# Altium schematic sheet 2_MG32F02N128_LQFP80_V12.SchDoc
size 513 x 335 mm
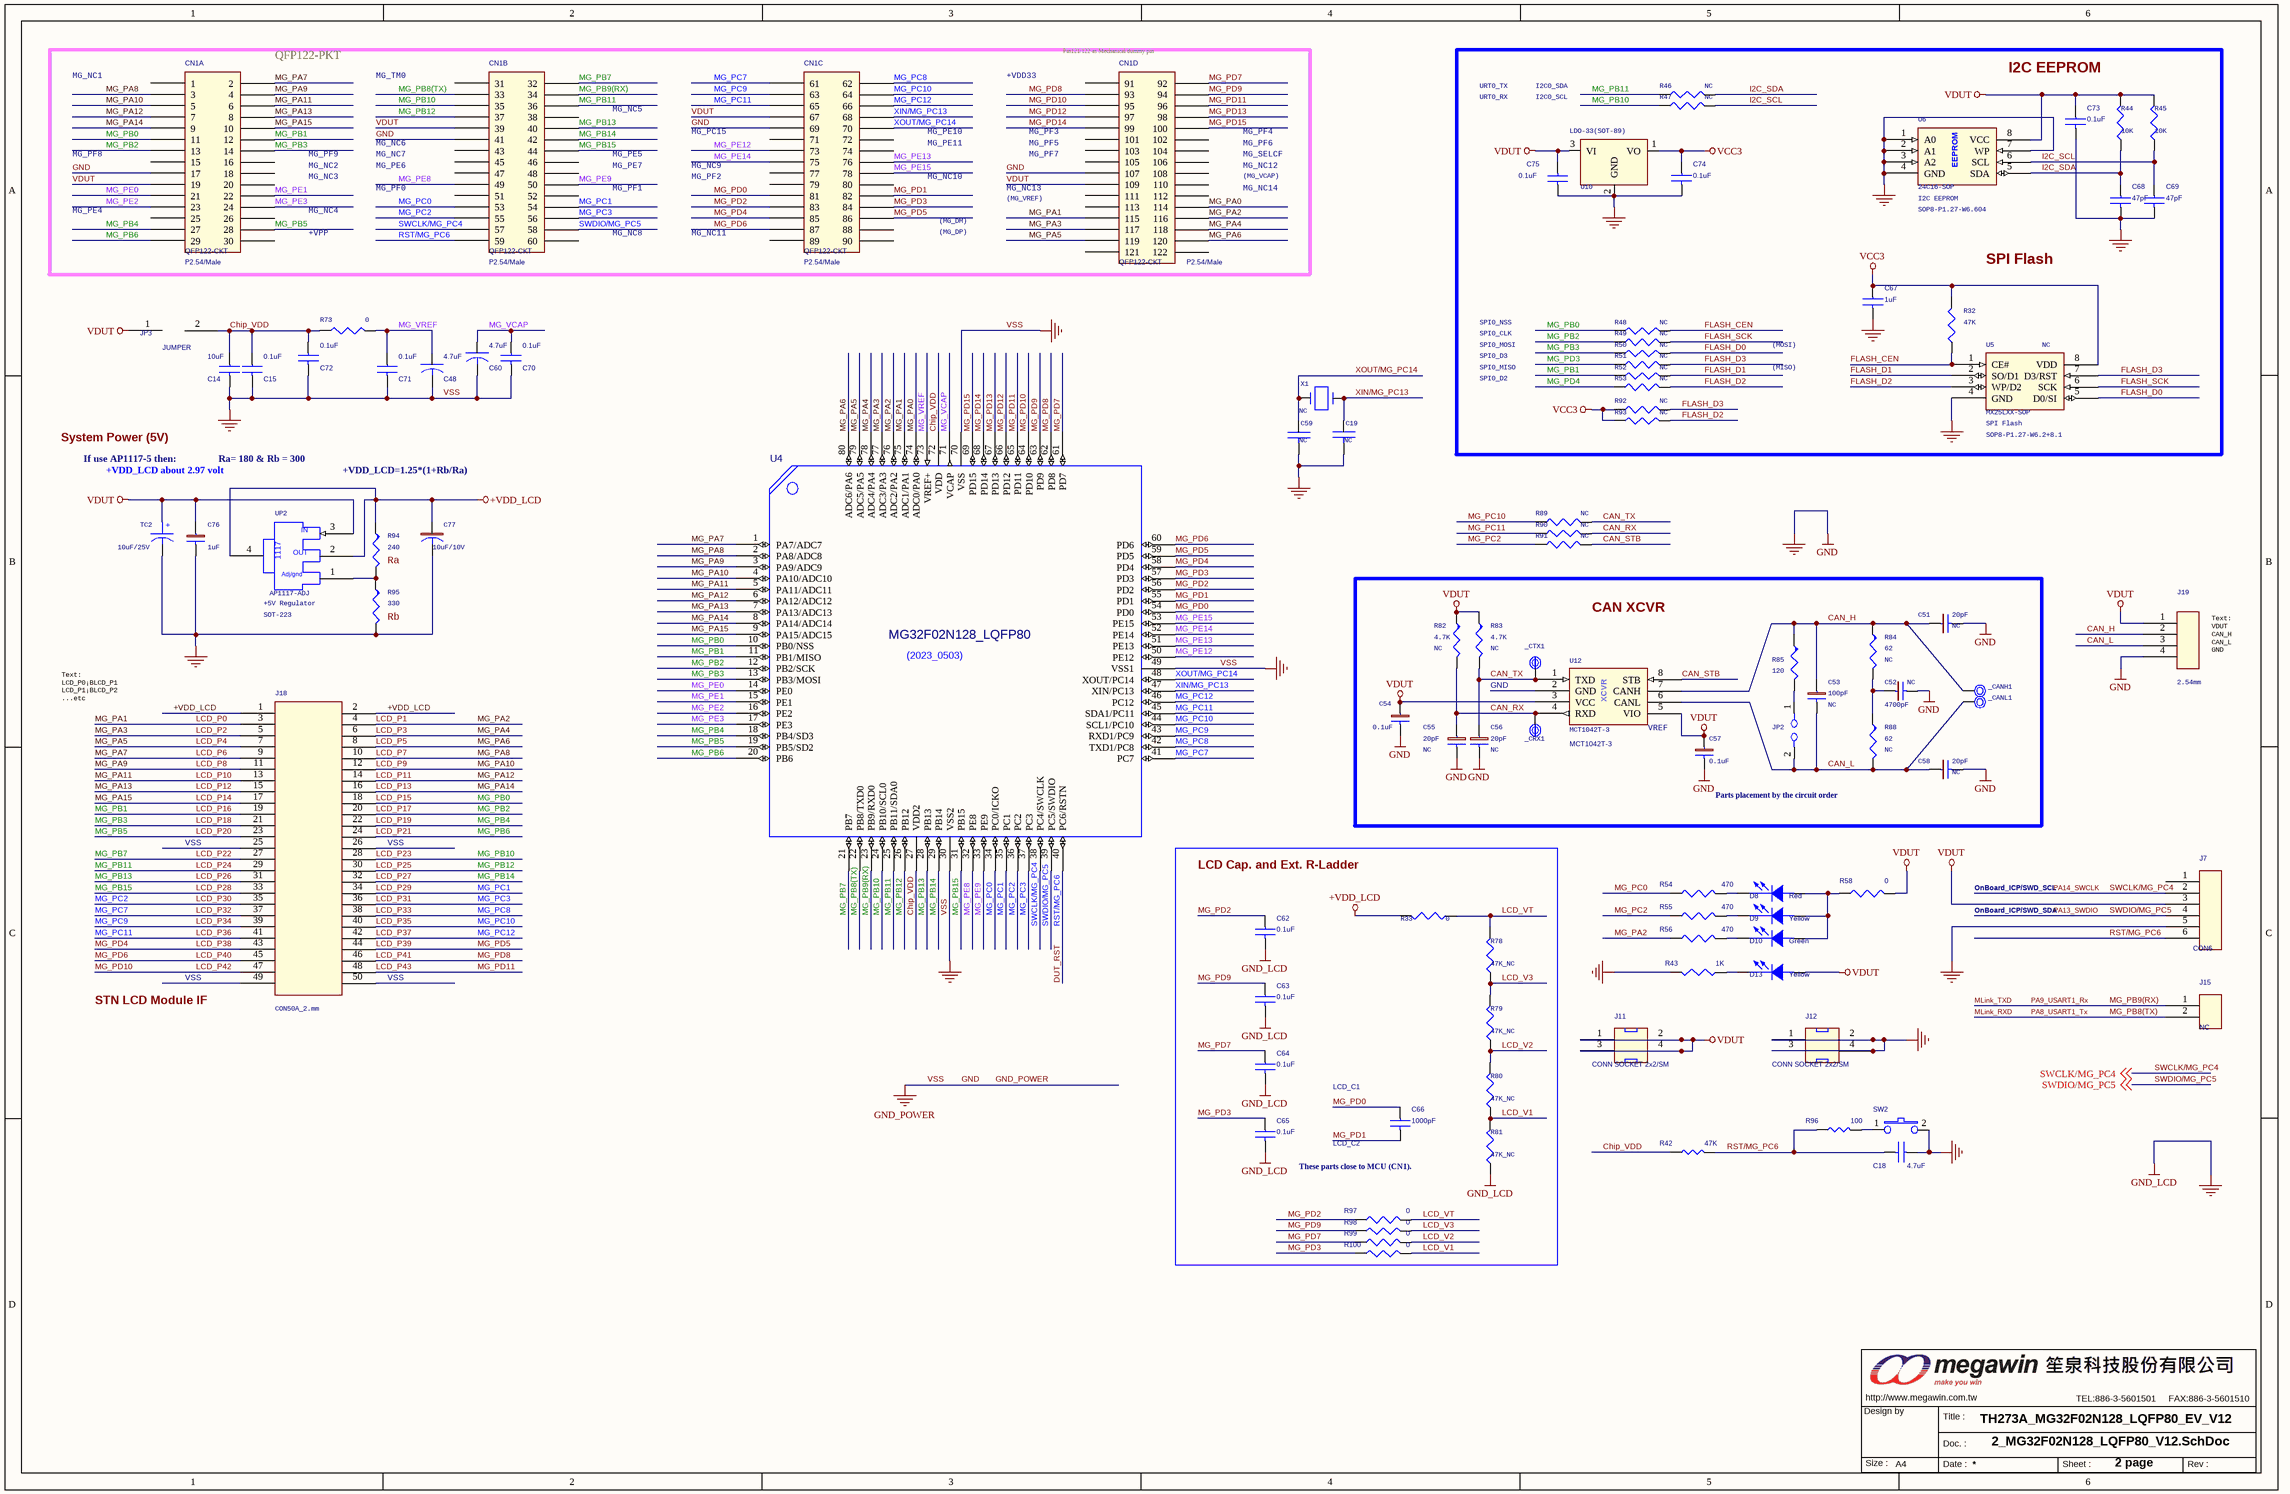
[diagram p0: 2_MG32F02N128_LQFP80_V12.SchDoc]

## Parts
_CANH1  TP-COIL  [TPH60-COIL]  (value not drawn)
_CANL1  TP-COIL  [TPH60-COIL]  (value not drawn)
_CRX1  TP-COIL  [TPH60-COIL]  (value not drawn)
_CTX1  TP-COIL  [TPH60-COIL]  (value not drawn)
C14  10uF  [C-0603]
C15  0.1uF  [C-0603]
C18  4.7uF  [C-0603]
C19  NC  [C-0603]
C48  4.7uF  [C-0805]
C51  20pF  Assembly: NC  [C-0603]
C52  4700pF  Assembly: NC  [C-0603]
C53  100pF  Assembly: NC  [C-0603]
C54  0.1uF  [C-0603]
C55  20pF  Assembly: NC  [C-0603]
C56  20pF  Assembly: NC  [C-0603]
C57  0.1uF  [C-0603]
C58  20pF  Assembly: NC  [C-0603]
C59  NC  [C-0603]
C60  4.7uF  [C-0805]
C62  0.1uF  [C-0603]
C63  0.1uF  [C-0603]
C64  0.1uF  [C-0603]
C65  0.1uF  [C-0603]
C66  1000pF  [C-0603]
C67  1uF  [C-0603]
C68  47pF  [C-0603]
C69  47pF  [C-0603]
C70  0.1uF  [C-0603]
C71  0.1uF  [C-0603]
C72  0.1uF  [C-0603]
C73  0.1uF  [C-0603]
C74  0.1uF  [C-0603]
C75  0.1uF  [C-0603]
C76  1uF  [C-0603]
C77  10uF/10V  [C-0805]
CN1  QFP122-CKT  Package: P2.54/Male  [QFP122-P2.54-CKT]  (parts A,B,C,D of 4)
D8  Red  [0805D]
D9  Yellow  [0805D]
D10  Green  [0805D]
D13  Yellow  [0805D]
J7  CON6  [PS6P254]
J11  CONN SOCKET 2x2/SM  [PS2X2P254]
J12  CONN SOCKET 2x2/SM  [PS2X2P254]
J15  NC  [PS2P254]
J18  CON50A_2.mm  [HD25X2-P2.0]
J19  2.54mm  [PS4P254]
JP2  JUMPER  [SIP2-P2.54-JUMPER]  (value not drawn)
JP3  JUMPER  [PS2P254]
MW1  OrgAddr3: TEL:886-3-5601501     FAX:886-3-5601510  [MEGAWIN_3.4_1]  (hidden comment: MW-A4)  (graphical)
R32  47K  [R-0603]
R33  0  [R-0603]
R42  47K  [R-0603]
R43  1K  [R-0603]
R44  10K  [R-0603]
R45  10K  [R-0603]
R46  NC  [R-0603]
R47  NC  [R-0603]
R48  NC  [R-0603]
R49  NC  [R-0603]
R50  NC  [R-0603]
R51  NC  [R-0603]
R52  NC  [R-0603]
R53  NC  [R-0603]
R54  470  [R-0603]
R55  470  [R-0603]
R56  470  [R-0603]
R58  0  [R-0603]
R73  0  [R-0603]
R78  47K_NC  [R-0603]
R79  47K_NC  [R-0603]
R80  47K_NC  [R-0603]
R81  47K_NC  [R-0603]
R82  4.7K  Assembly: NC  [R-0603]
R83  4.7K  Assembly: NC  [R-0603]
R84  62  Assembly: NC  [R-0603]
R85  120  [R-0603]
R88  62  Assembly: NC  [R-0603]
R89  NC  [R-0603]
R90  NC  [R-0603]
R91  NC  [R-0603]
R92  NC  [R-0603]
R93  NC  [R-0603]
R94  240  [R-0603]
R95  330  [R-0603]
R96  100  [R-0603]
R97  0  [R-0603]
R98  0  [R-0603]
R99  0  [R-0603]
R100  0  [R-0603]
SW2  SW TACT-SPST  [SW_T_2P]  (value not drawn)
TC2  10uF/25V  [C-1812+]
U4  MG32F02N128_LQFP80  [QFP80-P0.4-Z12X12]
U5  MX25LXX-SOP  Function: SPI Flash  Assembly: NC  [SOP8-P1.27-W6.2+8.1]
U6  24C16-SOP  Function: I2C EEPROM  [SOP8-P1.27-W6.604]
U10  LDO-33(SOT-89)  [SOT89]
U12  MCT1042T-3  [SOP8-P1.27-W6.2]
UP2  AP1117-ADJ  Package: SOT-223  Function: +5V Regulator  [SOT223H\3P]
X1  NC  [X49U]

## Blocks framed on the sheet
QFP122-PKT: CN1
CAN XCVR: _CANH1 _CANL1 _CRX1 _CTX1 C51-C58 JP2 R82-R85 R88 U12
LCD Cap. and Ext. R-Ladder: C62-C66 R33 R78-R81 R97-R100

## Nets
+VDD_LCD: C77.1 J18.1 J18.2 R33.2 R94.1 UP2.2(OUT) UP2.4(VOUT)
GND: C14.2 C15.2 C18.1 C19.2 C48.2 C51.2 C52.2 C54.2 C55.2 C56.2 C57.2 C58.2 C59.2 C60.2 C62.2 C63.2 C64.2 C65.2 C67.2 C68.2 C69.2 C70.2 C71.2 C72.2 C73.2 C74.2 C75.2 C76.2 C77.2 CN1.17 CN1.41 CN1.69 CN1.107 J7.5 J12.1 J12.2 J12.3 J12.4 J18.25 J18.26 J18.49 J18.50 J19.4 R43.1 R81.1 R95.2 SW2.2 TC2.2 U4.30(VSS2) U4.49(VSS1) U4.70(VSS) U5.4(GND) U6.1(A0) U6.2(A1) U6.3(A2) U6.4(GND) U6.7(WP) U10.2(GND) U12.2(GND)  [also labelled GND_LCD, GND_POWER, VSS]
VCC3: C67.1 C74.1 R32.2 R92.1 R93.1 U5.8(VDD) U10.1(VO)
VDUT: C54.1 C57.1 C73.1 C75.1 C76.1 CN1.19 CN1.39 CN1.67 CN1.109 D13.1(ANODE) J7.3 J11.1 J11.2 J11.3 J11.4 J19.1 JP3.1 R44.2 R45.2 R58.2 R82.1 R83.1 TC2.1 U6.8(VCC) U10.3(VI) U12.3(VCC) U12.5(VIO) UP2.3(IN)
CAN_H: _CANH1.1 C51.1 C53.1 J19.2 R84.1 R85.1 U12.7(CANH)
CAN_L: _CANL1.1 C53.2 C58.1 J19.3 JP2.2 R88.2 U12.6(CANL)
CAN_RX: _CRX1.1 C55.1 R82.2 R90.2 U12.4(RXD)
CAN_STB: R91.2 U12.8(STB)
CAN_TX: _CTX1.1 C56.1 R83.2 R89.2 U12.1(TXD)
Chip_VDD: C14.1 C15.1 C72.1 JP3.2 R42.1 R73.2 U4.27(VDD2) U4.72(VDD)
DUT_RST: C18.2 CN1.59 J7.6 R42.2 R96.1 U4.40(PC6/RSTN)  [also labelled RST/MG_PC6]
FLASH_CEN: R32.1 R48.2 U5.1(CE#)
FLASH_D0: R50.2 U5.5(D0/SI)
FLASH_D1: R52.2 U5.2(SO/D1)
FLASH_D2: R53.2 R93.2 U5.3(WP/D2)
FLASH_D3: R51.2 R92.2 U5.7(D3/RST)
FLASH_SCK: R49.2 U5.6(SCK)
I2C_SCL: C69.1 R45.1 R47.2 U6.6(SCL)
I2C_SDA: C68.1 R44.1 R46.2 U6.5(SDA)
LCD_P0: CN1.115 J18.3 U4.75(ADC1/PA1)  [also labelled MG_PA1]
LCD_P1: CN1.116 J18.4 R56.1 U4.76(ADC2/PA2)  [also labelled MG_PA2]
LCD_P2: CN1.117 J18.5 U4.77(ADC3/PA3)  [also labelled MG_PA3]
LCD_P3: CN1.118 J18.6 U4.78(ADC4/PA4)  [also labelled MG_PA4]
LCD_P4: CN1.119 J18.7 U4.79(ADC5/PA5)  [also labelled MG_PA5]
LCD_P5: CN1.120 J18.8 U4.80(ADC6/PA6)  [also labelled MG_PA6]
LCD_P6: CN1.2 J18.9 U4.1(PA7/ADC7)  [also labelled MG_PA7]
LCD_P7: CN1.3 J18.10 U4.2(PA8/ADC8)  [also labelled MG_PA8]
LCD_P8: CN1.4 J18.11 U4.3(PA9/ADC9)  [also labelled MG_PA9]
LCD_P9: CN1.5 J18.12 U4.4(PA10/ADC10)  [also labelled MG_PA10]
LCD_P10: CN1.6 J18.13 U4.5(PA11/ADC11)  [also labelled MG_PA11]
LCD_P11: CN1.7 J18.14 U4.6(PA12/ADC12)  [also labelled MG_PA12]
LCD_P12: CN1.8 J18.15 U4.7(PA13/ADC13)  [also labelled MG_PA13]
LCD_P13: CN1.9 J18.16 U4.8(PA14/ADC14)  [also labelled MG_PA14]
LCD_P14: CN1.10 J18.17 U4.9(PA15/ADC15)  [also labelled MG_PA15]
LCD_P15: CN1.11 J18.18 R48.1 U4.10(PB0/NSS)  [also labelled MG_PB0]
LCD_P16: CN1.12 J18.19 R52.1 U4.11(PB1/MISO)  [also labelled MG_PB1]
LCD_P17: CN1.13 J18.20 R49.1 U4.12(PB2/SCK)  [also labelled MG_PB2]
LCD_P18: CN1.14 J18.21 R50.1 U4.13(PB3/MOSI)  [also labelled MG_PB3]
LCD_P19: CN1.27 J18.22 U4.18(PB4/SD3)  [also labelled MG_PB4]
LCD_P20: CN1.28 J18.23 U4.19(PB5/SD2)  [also labelled MG_PB5]
LCD_P21: CN1.29 J18.24 U4.20(PB6)  [also labelled MG_PB6]
LCD_P22: CN1.32 J18.27 U4.21(PB7)  [also labelled MG_PB7]
LCD_P23: CN1.35 J18.28 R47.1 U4.24(PB10/SCL0)  [also labelled MG_PB10]
LCD_P24: CN1.36 J18.29 R46.1 U4.25(PB11/SDA0)  [also labelled MG_PB11]
LCD_P25: CN1.37 J18.30 U4.26(PB12)  [also labelled MG_PB12]
LCD_P26: CN1.40 J18.31 U4.28(PB13)  [also labelled MG_PB13]
LCD_P27: CN1.42 J18.32 U4.29(PB14)  [also labelled MG_PB14]
LCD_P28: CN1.44 J18.33 U4.31(PB15)  [also labelled MG_PB15]
LCD_P29: CN1.54 J18.34 U4.35(PC1)  [also labelled MG_PC1]
LCD_P30: CN1.55 J18.35 R55.1 R91.1 U4.36(PC2)  [also labelled MG_PC2]
LCD_P31: CN1.56 J18.36 U4.37(PC3)  [also labelled MG_PC3]
LCD_P32: CN1.61 J18.37 U4.41(PC7)  [also labelled MG_PC7]
LCD_P33: CN1.62 J18.38 U4.42(TXD1/PC8)  [also labelled MG_PC8]
LCD_P34: CN1.63 J18.39 U4.43(RXD1/PC9)  [also labelled MG_PC9]
LCD_P35: CN1.64 J18.40 R89.1 U4.44(SCL1/PC10)  [also labelled MG_PC10]
LCD_P36: CN1.65 J18.41 R90.1 U4.45(SDA1/PC11)  [also labelled MG_PC11]
LCD_P37: CN1.66 J18.42 U4.46(PC12)  [also labelled MG_PC12]
LCD_P38: CN1.85 J18.43 R53.1 U4.58(PD4)  [also labelled MG_PD4]
LCD_P39: CN1.86 J18.44 U4.59(PD5)  [also labelled MG_PD5]
LCD_P40: CN1.87 J18.45 U4.60(PD6)  [also labelled MG_PD6]
LCD_P41: CN1.93 J18.46 U4.62(PD8)  [also labelled MG_PD8]
LCD_P42: CN1.95 J18.47 U4.64(PD10)  [also labelled MG_PD10]
LCD_P43: CN1.96 J18.48 U4.65(PD11)  [also labelled MG_PD11]
LCD_V1: R80.1 R81.2 R100.2
LCD_V2: R79.1 R80.2 R99.2
LCD_V3: R78.1 R79.2 R98.2
LCD_VT: R33.1 R78.2 R97.2
MG_PA0: CN1.114 U4.74(ADC0/PA0)
MG_PB8(TX): CN1.33 J15.2 U4.22(PB8/TXD0)  [also labelled MLink_RXD, PA8_USART1_Tx]
MG_PB9(RX): CN1.34 J15.1 U4.23(PB9/RXD0)  [also labelled MLink_TXD, PA9_USART1_Rx]
MG_PC0: CN1.53 R54.1 U4.34(PC0/ICKO)
MG_PD0: C66.1 CN1.81 U4.54(PD0)
MG_PD1: C66.2 CN1.82 U4.55(PD1)
MG_PD2: C62.1 CN1.83 R97.1 U4.56(PD2)
MG_PD3: C65.1 CN1.84 R51.1 R100.1 U4.57(PD3)
MG_PD7: C64.1 CN1.92 R99.1 U4.61(PD7)
MG_PD9: C63.1 CN1.94 R98.1 U4.63(PD9)
MG_PD12: CN1.97 U4.66(PD12)
MG_PD13: CN1.98 U4.67(PD13)
MG_PD14: CN1.99 U4.68(PD14)
MG_PD15: CN1.100 U4.69(PD15)
MG_PE0: CN1.21 U4.14(PE0)
MG_PE1: CN1.22 U4.15(PE1)
MG_PE2: CN1.23 U4.16(PE2)
MG_PE3: CN1.24 U4.17(PE3)
MG_PE8: CN1.49 U4.32(PE8)
MG_PE9: CN1.50 U4.33(PE9)
MG_PE12: CN1.73 U4.50(PE12)
MG_PE13: CN1.76 U4.51(PE13)
MG_PE14: CN1.75 U4.52(PE14)
MG_PE15: CN1.78 U4.53(PE15)
MG_VCAP: C60.1 C70.1 U4.71(VCAP)
MG_VREF: C48.1 C71.1 R73.1 U4.73(VREF+)
PA13_SWDIO: CN1.58 J7.4 U4.39(PC5/SWDIO) ; off-sheet SWDIO/MG_PC5  [also labelled SWDIO/MG_PC5]
PA14_SWCLK: CN1.57 J7.2 U4.38(PC4/SWCLK) ; off-sheet SWCLK/MG_PC4  [also labelled SWCLK/MG_PC4]
XIN/MG_PC13: C19.1 CN1.68 U4.47(XIN/PC13) X1.2
XOUT/MG_PC14: C59.1 CN1.70 U4.48(XOUT/PC14) X1.1
NetC52_1: C52.1 R84.2 R88.1
NetD8_1: D8.1(ANODE) D9.1(ANODE) D10.1(ANODE) R58.1
NetD8_2: D8.2(CATHODE) R54.2
NetD9_2: D9.2(CATHODE) R55.2
NetD10_2: D10.2(CATHODE) R56.2
NetD13_2: D13.2(CATHODE) R43.2
NetJP2_1: JP2.1 R85.2
NetR94_2: R94.2 R95.1 UP2.1(ADJ)
NetR96_2: R96.2 SW2.1

Not connected (* = marked no-connect by the designer): CN1 1 15 16 18 20 25 26 30 31 38 43 45 46 47 48 51 52 60 71 72 74 77 79 80 88 89 90 91 101 102 103 104 105 106 108 110 111 112 113 121 122; J7 1

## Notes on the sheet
- MG_NC1
- MG_TM0
- +VDD33
- (near CN1) Pin121/122 as Mechanical dummy pin
- URT0_RX
- URT0_TX
- I2C0_SDA
- I2C0_SCL
- I2C EEPROM
- MG_PF8
- MG_PF9
- MG_NC7
- MG_NC6
- MG_NC5
- MG_PE5
- MG_PC15
- MG_PE10
- MG_PE11
- MG_PF3
- MG_PF7
- MG_PF5
- MG_SELCF
- MG_PF4
- MG_PF6
- MG_PE4
- MG_NC2
- MG_NC4
- MG_NC3
- MG_PF0
- MG_PE6
- MG_PF1
- MG_PE7
- MG_NC9
- MG_PF2
- MG_NC10
- (MG_VREF)
- MG_NC13
- MG_NC12
- (MG_VCAP)
- MG_NC14
- +VPP
- MG_NC8
- MG_NC11
- (MG_DM)
- (MG_DP)
- SPI Flash
- SPI0_NSS
- SPI0_D3
- SPI0_CLK
- SPI0_MISO
- SPI0_D2
- SPI0_MOSI
- (MOSI)
- (MISO)
- System Power (5V)
- If use AP1117-5 then:
- +VDD_LCD about 2.97 volt
- Ra= 180 & Rb = 300
- +VDD_LCD=1.25*(1+Rb/Ra)
- (near R94) Ra
- (near R95) Rb
- (near J19) Text:
  VDUT
  CAN_H
  CAN_L
  GND
- Text:
  LCD_P0¡BLCD_P1
  LCD_P1¡BLCD_P2
  ...etc
- (near U12) VREF
- Parts placement by the circuit order
- OnBoard_ICP/SWD_SCL
- OnBoard_ICP/SWD_SDA
- STN LCD Module IF
- LCD_C1
- These parts close to MCU (CN1).
- LCD_C2
- TH273A_MG32F02N128_LQFP80_EV_V12
- 2 page

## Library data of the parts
_CANH1 _CANL1 _CRX1 _CTX1 = TPH60-COIL: Assembly: NC
C14 = CAP NP_Dup1_C14: Origin: Altium
C15 C70-C72 = CAP NP_Dup1_C15: Origin: Altium
C18 C62-C69 C73-C75 = CAP NP_Dup1_C18: Origin: Altium
C19 C59 = C NP
C48 C60 = CAP_C9: Origin: Altium
C51-C58 = CAP-NP
C76 = CAP-NP: 2ND PART FIELD: SMD_0805
C77 = CAP-POL
CN1 = QFP122-CKT_CN1: Origin: Altium
D8 = LED_D8: Origin: Altium
D9 = LED_D9: Origin: Altium
D10 = LED_D10: Origin: Altium
D13 = LED_D13: Origin: Altium
J7 = CON6_Dup1_J7: Origin: Altium
J11 = CONN SOCKET 2x2/SM_J11: Origin: Altium
J12 = CONN SOCKET 2x2/SM_J12: Origin: Altium
J15 = CON2_J8: Origin: Altium
J18 = CON50A
J19 = CON4
JP3 = JUMPER_JP3: Origin: Altium
MW1 = MW_A4_2
R32 R33 R44-R53 R73 R78-R81 R89-R93 = R_Dup1
R42 R96 = R_Dup3_R42: Origin: Altium
R43 = R_Dup4_R43: Origin: Altium
R54 R97-R100 = R_Dup4_R54: Origin: Altium
R55 = R_Dup4_R55: Origin: Altium
R56 = R_Dup4_R56: Origin: Altium
R58 = R_Dup4_R58: Origin: Altium
R82-R85 R88 = R_Dup2
R94 R95 = R_Dup2: 2ND PART FIELD: SMD_0805
SW2 = SW TACT-SPST_SW2: Origin: Altium
TC2 = CAP-EC
U4 = IC-MG32F02K128-LQFP80: SPLIT_INST: TRUE; SWAP_INFO: (S1+S2); OriginalSymbolOrigin: (0,0); Designator: A
U5 = ICM-25LXX
U6 = ICM-24CXX: 1ST PART FIELD: OSD Record Buffer; 2ND PART FIELD: SOP_8PIN; Assembly: NC
U10 = AIC1722-33
U12 = IC-TCAN1462
UP2 = ICP-AP1117
X1 = CRYSTAL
